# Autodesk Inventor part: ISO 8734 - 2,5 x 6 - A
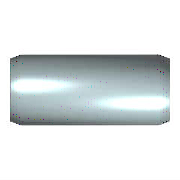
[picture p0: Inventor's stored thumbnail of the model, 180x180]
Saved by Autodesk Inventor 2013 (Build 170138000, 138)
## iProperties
Created: 2012-02
Part Number: ISO 8734 - 2,5 x 6 - A
Material: Stahl
Description: Zylinderstift
Document SubType Name: Modeling
Standard: ISO 8734
Designer: rYan
Standards Organization: DIN
Language: de-DE
Size Designation: 2,5 x 6 - A
Categories: <MemberInstance><Categories><Category DisplayName="Verbindungselemente" InternalName="e4da775c-781d-43d5-af7c-5136215cf5a6" Mnemonic="FSTN"><Category DisplayNam
Density: 7.85 g/cm^3
IsCustomPart: 0
Author: rYan
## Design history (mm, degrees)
sketch "Skizze"
  geometry: C1 r 1.25 at (0, 0); 1 further point
  constraints: 1 centre point, 1 coincident
  dimensions: "d1" = 2.5 diameter of C1 (= NND)
extrude "Körper" new body sketch "Skizze" distance "d2" = 6 (= NLG); taper "d3" = 0 deg
body "Solid1"
chamfer "Fase1" distance "d4" = 0.4 (= PHH); stored, may be unused: angle "d5" = 15 deg (= FAWI), second distance "d11" = 0.4 (= PHH)
chamfer "Fase2" distance "d8" = 0.4 (= PHH); stored, may be unused: angle "d9" = 15 deg (= FAWI), second distance "d12" = 0.4 (= PHH)
other parameters: "NND" = 2.5 [user parameter; used in 1 equation term], "NLG" = 6 [user parameter; used in 1 equation term], "PHH" = 0.4 [user parameter; used in 5 equation terms], "FAWI" = 15 deg [user parameter; used in 2 equation terms], "d13" = 0, "d15" = 0, "d16" = 0, "PHH2" = 0.4 (= PHH) [user parameter], "FAWI2" = 15 deg [user parameter]
